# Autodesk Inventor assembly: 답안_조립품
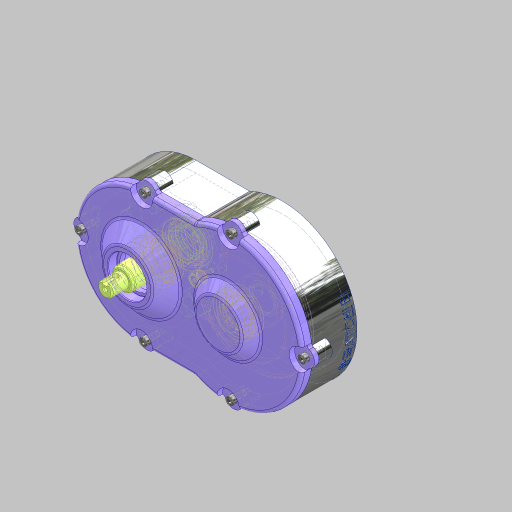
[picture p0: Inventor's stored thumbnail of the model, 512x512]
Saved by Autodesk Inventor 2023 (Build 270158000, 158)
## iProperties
Created: 2025-09
Part Number: 답안_조립품
Document SubType Name: Assembly
Designer: home
Author: home
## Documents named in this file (19)
- C:\Users\home\Desktop\750903v1014\답안_조립품.iam
- C:\Users\home\Desktop\750903v1014\본체.ipt
- C:\Users\home\Desktop\750903v1014\평행 키 6x6x14.ipt
- C:\Users\home\Desktop\750903v1014\평 와셔 M3.ipt
- C:\Users\home\Desktop\750903v1014\커버.ipt
- C:\Users\home\Desktop\750903v1014\캠 플로워.ipt
- C:\Users\home\Desktop\750903v1014\칼라.ipt
- C:\Users\home\Desktop\750903v1014\육각 너트 M3.ipt
- C:\Users\home\Desktop\750903v1014\오일 실 20 35 8.ipt
- C:\Users\home\Desktop\750903v1014\어댑터.ipt
- C:\Users\home\Desktop\750903v1014\슬롯.ipt
- C:\Users\home\Desktop\750903v1014\슬롯 축.ipt
- C:\Users\home\Desktop\750903v1014\스프링 와셔 M3.ipt
- C:\Users\home\Desktop\750903v1014\스러스트 볼 베어링 51102.ipt
- C:\Users\home\Desktop\750903v1014\깊은 홈 볼 베어링 6904.ipt
- C:\Users\home\Desktop\750903v1014\구동 휠.ipt
- C:\Users\home\Desktop\750903v1014\구동 축.ipt
- C:\Users\home\Desktop\750903v1014\6각 구멍붙이 볼트 M6x12.ipt
- C:\Users\home\Desktop\750903v1014\6각 구멍붙이 볼트 M4x10.ipt
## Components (9 placed, 4 different names)
1. 구동 축:1
2. 구동 휠:1 — 각도:1
3. 6각 구멍붙이 볼트 M6x12:1
4. 6각 구멍붙이 볼트 M4x10:1
5. 6각 구멍붙이 볼트 M4x10:2
6. 6각 구멍붙이 볼트 M4x10:3
7. 6각 구멍붙이 볼트 M4x10:4
8. 6각 구멍붙이 볼트 M4x10:6
9. 6각 구멍붙이 볼트 M4x10:8
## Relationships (1: Angle 1)
- 각도:1 [Angle]: 구동 휠:1
